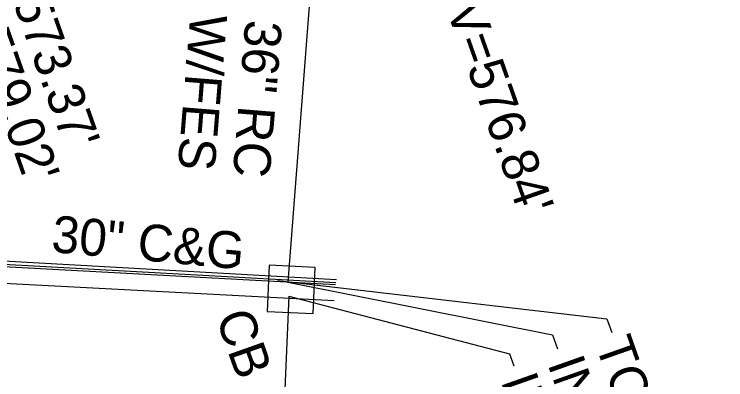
# Model space of a CAD drawing. Extents: x 2004847 to 2009016, y 1134161 to 1140101.
# Drawn here: x 2007596.8 to 2007673.9, y 1137729.8 to 1137769.4 of the extents above; entities that cross this region are included whole.
import ezdxf

# ---------------------------------------------------------------- set-up
doc = ezdxf.new("R2010")
doc.units = 0
for name, color, linetype in [('RD_EX_Curb', 7, 'Continuous'), ('RD_EX_DR_Inlet', 7, 'Continuous'), ('RD_EX_DR_Inlet_txCode', 7, 'Continuous'), ('RD_EX_DR_Pipe', 7, 'Continuous'), ('RD_EX_DR_Pipe_txCode', 7, 'Continuous'), ('RD_EX_Road', 7, 'Continuous'), ('RD_Sketch3', 7, 'Continuous')]:
    doc.layers.add(name, color=color, linetype=linetype)

msp = doc.modelspace()

# ---------------------------------------------------------------- linework, layer by layer
at = {"layer": 'RD_EX_Curb'}
for p, q in [((2007584.089, 1137743.349), (2007631.709, 1137740.662)), ((2007631.589, 1137740.068), (2007584.076, 1137742.656)), ((2007584.091, 1137742.959), (2007631.63, 1137740.334))]:
    msp.add_line(p, q, dxfattribs=at)
at = {"layer": 'RD_EX_DR_Inlet'}
msp.add_line((2007629.171, 1137736.969), (2007629.405, 1137741.964), dxfattribs=at)
msp.add_lwpolyline([(2007629.171, 1137736.969), (2007629.405, 1137741.964), (2007624.411, 1137742.199), (2007624.176, 1137737.204)], close=True, dxfattribs=at)
at = {"layer": 'RD_EX_DR_Inlet_txCode'}
for points in [[(2007625.301, 1137740.535), (2007661.013, 1137736.4), (2007661.544, 1137734.896)], [(2007626.424, 1137740.378), (2007655.119, 1137734.645), (2007655.651, 1137733.14)], [(2007626.539, 1137738.853), (2007650.464, 1137732.61), (2007650.934, 1137731.279)]]:
    msp.add_lwpolyline(points, dxfattribs=at)
at = {"layer": 'RD_EX_DR_Pipe'}
for p, q in [((2007629.628, 1137781.754), (2007626.424, 1137740.378)), ((2007626.539, 1137738.853), (2007624.513, 1137690.78))]:
    msp.add_line(p, q, dxfattribs=at)
at = {"layer": 'RD_EX_Road'}
msp.add_line((2007583.943, 1137740.878), (2007631.437, 1137738.37), dxfattribs=at)

# ---------------------------------------------------------------- texts
at = {"layer": 'RD_EX_DR_Inlet_txCode'}
for s, height, p in [("INV=573.37'", 4.00001, (2007592.593, 1137782.181)), ("TOP=579.02'", 4.00001, (2007587.534, 1137780.496)), ("INV=576.84'", 4.00001, (2007641.785, 1137775.045)), ('CB', 4, (2007618.572, 1137736.591)), ("TOP=582.42'", 4.00001, (2007659.719, 1137733.643)), ("INV=577.05'", 4.00001, (2007654.54, 1137731.523)), ("INV=577.39'", 4.00001, (2007649.475, 1137729.662))]:
    msp.add_text(s, height=height, rotation=289.44941, dxfattribs=at).set_placement(p)
at = {"layer": 'RD_EX_DR_Pipe_txCode'}
for s, p in [('W/FES', (2007615.866, 1137769.553)), ('36" RC ', (2007621.833, 1137768.91))]:
    msp.add_text(s, height=4, rotation=265.34758, dxfattribs=at).set_placement(p)
at = {"layer": 'RD_Sketch3'}
msp.add_text('30" C&G', height=4, rotation=354.71413, dxfattribs=at).set_placement((2007600.708, 1137743.656))

doc.saveas('drawing.dxf')
